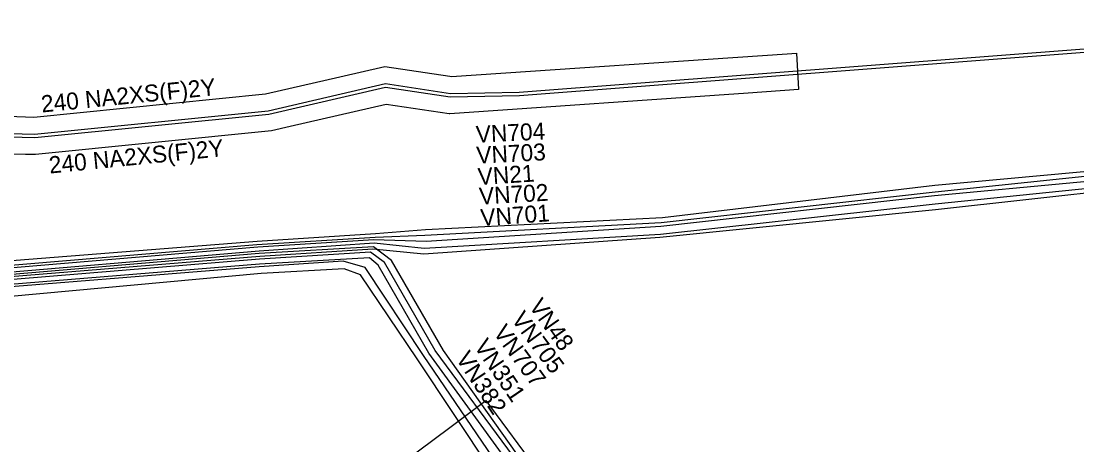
# Model space of a CAD drawing. Extents: x -545588 to -543214, y -1196037 to -1194452.
# Drawn here: x -545262.7 to -545200.6, y -1194915.7 to -1194890.7 of the extents above; entities that cross this region are included whole.
import ezdxf

# ---------------------------------------------------------------- set-up
doc = ezdxf.new("R2010")
doc.units = 0
for name, color, linetype in [('CIZÍ_NADZEM', 7, 'Continuous'), ('Vrstva 35', 7, 'Continuous'), ('ZP_EON', 7, 'Continuous'), ('ZP_EON_POPIS', 7, 'Continuous')]:
    doc.layers.add(name, color=color, linetype=linetype)

msp = doc.modelspace()

# ---------------------------------------------------------------- linework, layer by layer
at = {"layer": 'Vrstva 35'}
for points in [[(-545264.03, -1194896.28), (-545262.5, -1194896.33), (-545261.991, -1194896.349), (-545248.359, -1194894.982), (-545243.97, -1194893.97), (-545241.333, -1194893.361), (-545237.5, -1194893.94), (-545237.397, -1194893.959), (-545217.62, -1194892.62), (-545217.07, -1194892.58), (-545216.95, -1194894.72), (-545219.93, -1194894.93), (-545237.5, -1194896.16), (-545237.543, -1194896.161), (-545241.247, -1194895.599), (-545246.91, -1194896.91), (-545248.001, -1194897.158), (-545261.909, -1194898.551), (-545262.5, -1194898.55), (-545267.99, -1194898.54)], [(-545245.95, -1194920.95), (-545237.5, -1194914.64), (-545235.38, -1194913.06), (-545225.9, -1194925.9)]]:
    msp.add_lwpolyline(points, dxfattribs=at)
at = {"layer": 'ZP_EON'}
for points in [[(-545268.613, -1194897.38), (-545261.946, -1194897.55), (-545248.164, -1194896.169), (-545241.286, -1194894.582), (-545237.477, -1194895.16), (-545233.395, -1194895.08), (-545178.862, -1194890.89)], [(-545268.587, -1194897.18), (-545261.954, -1194897.35), (-545248.196, -1194895.971), (-545241.294, -1194894.378), (-545237.463, -1194894.96), (-545233.405, -1194894.88), (-545178.878, -1194890.69)], [(-545192.21, -1194899.03), (-545208.9, -1194900.78), (-545225.05, -1194902.59), (-545238.97, -1194903.32), (-545241.89, -1194903.44), (-545248.86, -1194903.88), (-545267.1, -1194905.41)], [(-545192.24, -1194898.85), (-545208.93, -1194900.39), (-545224.97, -1194902.29), (-545238.93, -1194902.99), (-545241.87, -1194903.23), (-545248.84, -1194903.69), (-545267.05, -1194905.12)], [(-545192.21, -1194899.78), (-545208.91, -1194901.48), (-545225.09, -1194903.27), (-545239.01, -1194904.09), (-545241.95, -1194903.79), (-545248.73, -1194904.26), (-545267.223, -1194905.818)], [(-545192.17, -1194899.42), (-545208.95, -1194900.99), (-545225.07, -1194902.79), (-545238.89, -1194903.69), (-545241.97, -1194903.58), (-545248.8, -1194904.02), (-545267.18, -1194905.57)], [(-545192.22, -1194899.97), (-545208.89, -1194901.81), (-545225.13, -1194903.44), (-545239.03, -1194904.43), (-545242.04, -1194904.14), (-545248.68, -1194904.56), (-545267.25, -1194906.09)], [(-545233.55, -1194916.21), (-545237.86, -1194910.11), (-545240.94, -1194904.81), (-545241.99, -1194903.99), (-545248.73, -1194904.4), (-545267.223, -1194905.96)], [(-545233.75, -1194916.35), (-545238.35, -1194910.11), (-545241.34, -1194904.93), (-545242.16, -1194904.31), (-545248.71, -1194904.72), (-545267.29, -1194906.26)], [(-545234.13, -1194916.6), (-545238.74, -1194910.26), (-545241.72, -1194905.08), (-545242.22, -1194904.65), (-545248.71, -1194905.01), (-545267.267, -1194906.539)], [(-545234.65, -1194916.87), (-545239.05, -1194910.4), (-545242.48, -1194905.21), (-545243.78, -1194904.85), (-545248.72, -1194905.18), (-545267.26, -1194906.67)], [(-545235.07, -1194917.17), (-545239.41, -1194910.6), (-545242.76, -1194905.64), (-545243.71, -1194905.29), (-545248.61, -1194905.57), (-545267.22, -1194907.27)]]:
    msp.add_lwpolyline(points, dxfattribs=at)

# ---------------------------------------------------------------- texts
at = {"layer": 'CIZÍ_NADZEM'}
for s, rotation, p in [('VN704', 2.871, (-545235.939, -1194897.869)), ('VN703', 3.002, (-545235.904, -1194899.101)), ('VN21', 3.726, (-545235.817, -1194900.362)), ('VN702', 3.371, (-545235.744, -1194901.514)), ('VN701', 4.074, (-545235.657, -1194902.78)), ('VN48', 305.243, (-545232.874, -1194907.494)), ('VN705', 306.397, (-545233.91, -1194908.274)), ('VN707', 306.022, (-545234.979, -1194909.049)), ('VN351', 304.218, (-545236.106, -1194909.86)), ('VN382', 303.448, (-545237.178, -1194910.576))]:
    msp.add_text(s, height=1, rotation=rotation, dxfattribs=at).set_placement(p)
at = {"layer": 'ZP_EON_POPIS'}
for rotation, p in [(5.724, (-545261.522, -1194896.081)), (5.722, (-545261.059, -1194899.679))]:
    msp.add_text('240 NA2XS(F)2Y', height=1, rotation=rotation, dxfattribs=at).set_placement(p)

doc.saveas('drawing.dxf')
